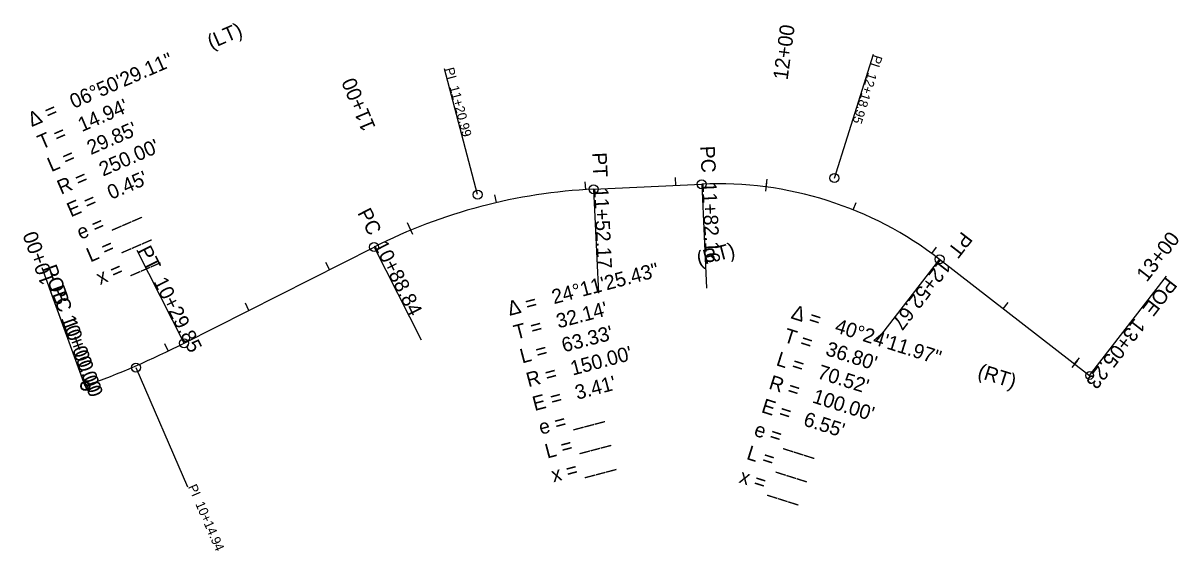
# Model space of a CAD drawing. Extents: x 21487961 to 21488281, y 8075161 to 8075307.
import ezdxf

# ---------------------------------------------------------------- set-up
doc = ezdxf.new("R2010")
doc.units = 0
for name, color, linetype in [('Terrain', 7, 'Continuous'), ('TextAlignment', 7, 'Continuous'), ('TextAlignmentLrg', 7, 'Continuous'), ('TextAlignmentSml', 7, 'Continuous')]:
    doc.layers.add(name, color=color, linetype=linetype)

msp = doc.modelspace()

# ---------------------------------------------------------------- linework, layer by layer
at = {"layer": 'Terrain'}
for p, q in [((21488119.14, 8075260.68), (21488149.09, 8075262.07)), ((21488005.72, 8075218.03), (21488058.36, 8075244.67)), ((21488214.95, 8075241.26), (21488256.51, 8075209.08))]:
    msp.add_line(p, q, dxfattribs=at)
for centre, radius, start, end in [((21488126.1, 8075110.84), 150, 92.6592, 116.8495), ((21488153.73, 8075162.18), 100, 52.2558, 92.6592), ((21487892.81, 8075441.08), 250, 290.0081, 296.8495)]:
    msp.add_arc(centre, radius, start, end, dxfattribs=at)
at = {"layer": 'TextAlignment'}
for p, q in [((21488185.85, 8075263.78), (21488196.7, 8075298.11)), ((21488087.03, 8075259.19), (21488077.87, 8075294)), ((21488119.14, 8075260.68), (21488120.48, 8075231.91)), ((21488149.09, 8075262.07), (21488150.43, 8075233.3)), ((21488005.72, 8075218.03), (21487992.72, 8075243.72)), ((21488058.36, 8075244.67), (21488071.36, 8075218.98)), ((21488214.95, 8075241.26), (21488197.32, 8075218.48)), ((21487978.35, 8075206.17), (21487966.44, 8075238.87)), ((21488256.51, 8075209.08), (21488277.81, 8075236.6)), ((21487978.35, 8075206.17), (21487968.5, 8075233.23)), ((21487992.39, 8075211.28), (21488006.7, 8075178.25))]:
    msp.add_line(p, q, dxfattribs=at)
for centre, radius in [((21488149.09, 8075262.07), 1.25), ((21488185.85, 8075263.78), 1.25), ((21488087.03, 8075259.19), 1.25), ((21488119.14, 8075260.68), 1.25), ((21488058.36, 8075244.67), 1.25), ((21488214.95, 8075241.26), 1.25), ((21488005.72, 8075218.03), 1.25), ((21487992.39, 8075211.28), 1.25), ((21488256.51, 8075209.08), 1.07), ((21487978.35, 8075206.17), 1.25), ((21487978.35, 8075206.17), 1.07)]:
    msp.add_circle(centre, radius, dxfattribs=at)
at = {"layer": 'TextAlignmentLrg'}
for p, q in [((21488166.9, 8075261.31), (21488167.19, 8075263.47)), ((21488068.49, 8075249.34), (21488067.65, 8075251.35)), ((21488252.37, 8075212.28), (21488253.71, 8075214.01)), ((21487977.93, 8075207.32), (21487978.77, 8075205.02))]:
    msp.add_line(p, q, dxfattribs=at)
at = {"layer": 'TextAlignmentSml'}
for p, q in [((21488141.95, 8075261.74), (21488141.84, 8075263.92)), ((21488116.97, 8075260.56), (21488116.84, 8075262.74)), ((21488167.06, 8075262.52), (21488166.74, 8075260.1)), ((21488092.26, 8075256.98), (21488091.77, 8075259.1)), ((21488191.01, 8075254.97), (21488191.83, 8075257)), ((21488068.02, 8075250.47), (21488068.96, 8075248.21)), ((21488212.81, 8075242.86), (21488214.1, 8075244.62)), ((21488046, 8075238.42), (21488045.02, 8075240.37)), ((21488023.7, 8075227.13), (21488022.71, 8075229.08)), ((21488232.6, 8075227.59), (21488233.94, 8075229.31)), ((21488001.37, 8075215.88), (21488000.43, 8075217.85)), ((21488253.12, 8075213.25), (21488251.62, 8075211.32)), ((21487977.93, 8075207.32), (21487978.77, 8075205.02))]:
    msp.add_line(p, q, dxfattribs=at)

# ---------------------------------------------------------------- texts
at = {"layer": 'TextAlignment'}
for s, height, rotation, p in [(' (LT)', 4.008, 23.4288, (21488011.88, 8075298.83)), ('06°50\'29.11"', 4.008, 23.4288, (21487975.17, 8075282.93)), ('PI ', 2.592, 252.4575, (21488196.75, 8075298.09)), ('PI ', 2.592, 284.7543, (21488077.92, 8075294.02)), ('12+18.95', 2.592, 252.4575, (21488195.19, 8075293.16)), ('11+20.99', 2.592, 284.7543, (21488079.23, 8075289.02)), ("14.94'", 4.008, 23.4288, (21487977.42, 8075276.48)), ('Δ = ', 4.008, 23.4288, (21487963.53, 8075277.88)), ("29.85'", 4.008, 23.4288, (21487979.9, 8075270.13)), ('T = ', 4.008, 23.4288, (21487966.24, 8075271.63)), ("250.00'", 4.008, 23.4288, (21487983.28, 8075264.16)), ('L = ', 4.008, 23.4288, (21487968.95, 8075265.38)), ('PT', 4.008, 272.6592, (21488118.75, 8075270.79)), ('PC', 4.008, 272.6592, (21488148.68, 8075272.6)), ('R = ', 4.008, 23.4288, (21487971.66, 8075259.13)), ("0.45'", 4.008, 23.4288, (21487985.55, 8075257.72)), ('11+52.17', 4.008, 272.6592, (21488119.2, 8075261.1)), ('11+82.16', 4.008, 272.6592, (21488149.15, 8075262.64)), ('E = ', 4.008, 23.4288, (21487974.37, 8075252.87)), ('PC', 4.008, 296.8495, (21488053.65, 8075254.15)), ('e = ___ ', 4.008, 23.4288, (21487977.08, 8075246.62)), ('L = ___', 4.008, 23.4288, (21487979.78, 8075240.37)), ('PT', 4.008, 232.2558, (21488221.2, 8075249.21)), ('PT', 4.008, 296.8495, (21487992.79, 8075243.76)), ('10+88.84', 4.008, 296.8495, (21488058.15, 8075245.25)), (' (RT)', 4.008, 14.7543, (21488146.84, 8075239.01)), ('x = ___', 4.008, 23.4288, (21487982.49, 8075234.12)), ('12+52.67', 4.008, 232.2558, (21488215.26, 8075241.54)), ('POB ', 4.008, 290.0081, (21487966.52, 8075238.89)), ('24°11\'25.43"', 4.008, 14.7543, (21488108.15, 8075228.82)), ('PC', 4.008, 290.0081, (21487968.57, 8075233.25)), ('10+29.85', 4.008, 296.8495, (21487997.16, 8075235.11)), ('POE ', 4.008, 232.2558, (21488277.87, 8075236.55)), ('Δ = ', 4.008, 14.7543, (21488095.88, 8075225.59)), ("32.14'", 4.008, 14.7543, (21488109.4, 8075222.11)), ('Δ = ', 4.008, 342.4575, (21488173.58, 8075224.96)), ('10+00.00', 4.008, 290.0081, (21487971.58, 8075224.98)), ('10+00.00', 4.008, 290.0081, (21487971.98, 8075223.88)), ('13+05.23', 4.008, 232.2558, (21488269.07, 8075225.18)), ('T = ', 4.008, 14.7543, (21488097.62, 8075219)), ("63.33'", 4.008, 14.7543, (21488110.9, 8075215.46)), ('T = ', 4.008, 342.4575, (21488171.52, 8075218.46)), ('40°24\'11.97"', 4.008, 342.4575, (21488185.68, 8075221.13)), ("36.80'", 4.008, 342.4575, (21488183.14, 8075214.79)), ('L = ', 4.008, 14.7543, (21488099.35, 8075212.41)), ("150.00'", 4.008, 14.7543, (21488113.34, 8075209.05)), ('L = ', 4.008, 342.4575, (21488169.47, 8075211.97)), ("70.52'", 4.008, 342.4575, (21488180.85, 8075208.37)), (' (RT)', 4.008, 342.4575, (21488223.82, 8075209.08)), ('R = ', 4.008, 14.7543, (21488101.09, 8075205.83)), ("3.41'", 4.008, 14.7543, (21488114.61, 8075202.34)), ('R = ', 4.008, 342.4575, (21488167.42, 8075205.47)), ('E = ', 4.008, 14.7543, (21488102.82, 8075199.24)), ('E = ', 4.008, 342.4575, (21488165.36, 8075198.97)), ("100.00'", 4.008, 342.4575, (21488179.5, 8075201.65)), ("6.55'", 4.008, 342.4575, (21488176.99, 8075195.3)), ('e = ___ ', 4.008, 14.7543, (21488104.56, 8075192.65)), ('e = ___ ', 4.008, 342.4575, (21488163.31, 8075192.47)), ('L = ___', 4.008, 14.7543, (21488106.29, 8075186.06)), ('L = ___', 4.008, 342.4575, (21488161.26, 8075185.98)), ('x = ___', 4.008, 14.7543, (21488108.03, 8075179.47)), ('x = ___', 4.008, 342.4575, (21488159.2, 8075179.48)), ('PI ', 2.592, 293.4288, (21488006.75, 8075178.27)), ('10+14.94', 2.592, 293.4288, (21488008.8, 8075173.53))]:
    msp.add_text(s, height=height, rotation=rotation, dxfattribs=at).set_placement(p)
at = {"layer": 'TextAlignmentLrg'}
msp.add_text('10+00', height=4.08, rotation=110.0081, dxfattribs=at).set_placement((21487970, 8075235.05))
at = {"layer": 'TextAlignmentSml'}
for s, rotation, p in [('12+00', 82.4349, (21488172.87, 8075290.78)), ('11+00', 112.5882, (21488058.85, 8075277.82)), ('10+00', 110.0081, (21487970, 8075235.05)), ('13+00', 52.2558, (21488272.35, 8075234.76))]:
    msp.add_text(s, height=4.08, rotation=rotation, dxfattribs=at).set_placement(p)

doc.saveas('drawing.dxf')
